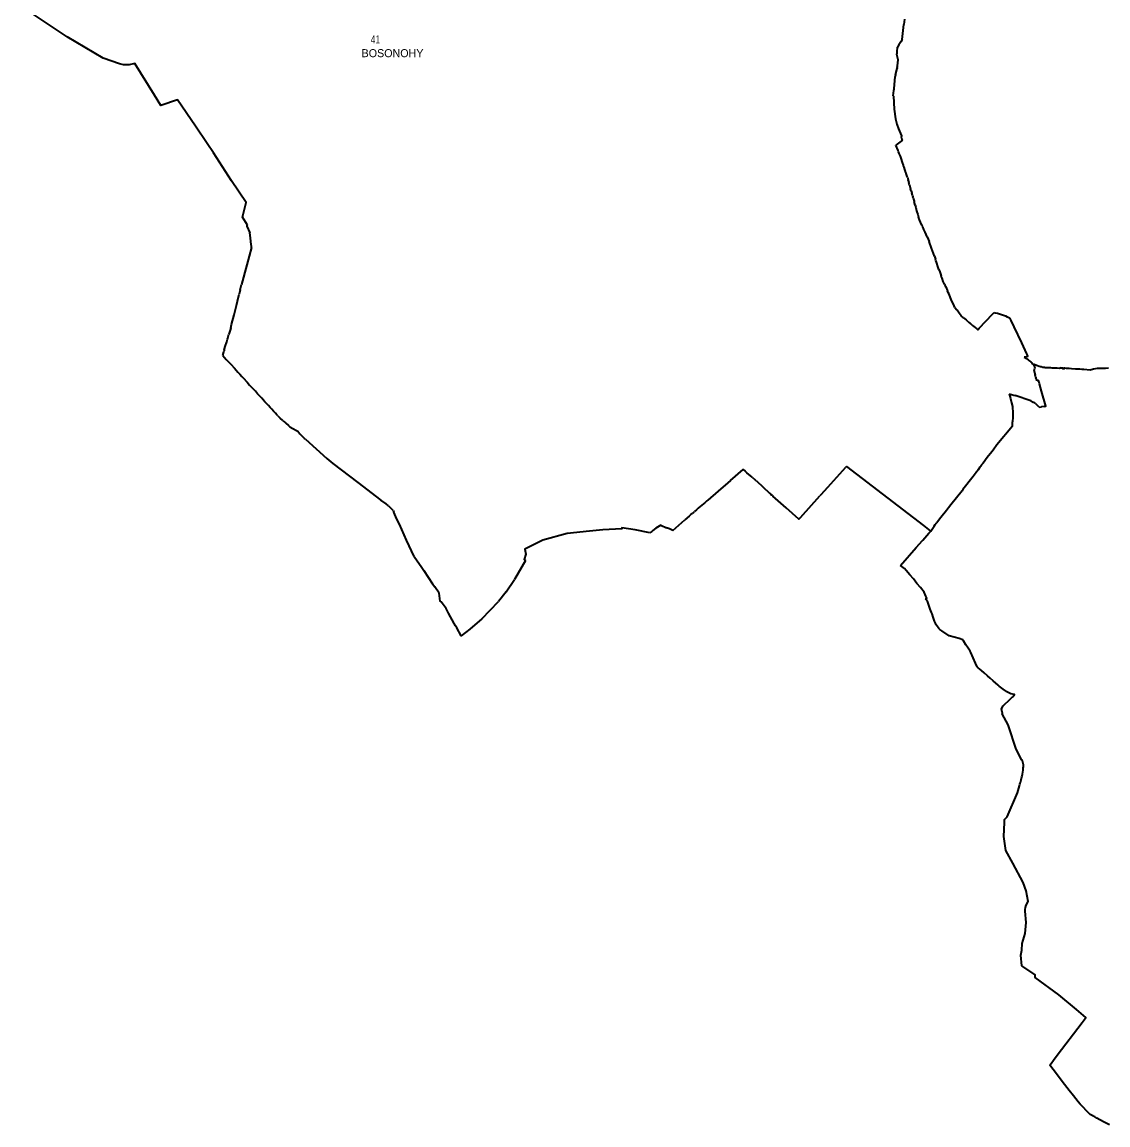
# Model space of a CAD drawing. Extents: x -610940 to -588976, y -1170376 to -1149800.
# Drawn here: x -605598 to -602206, y -1165066 to -1161621 of the extents above; entities that cross this region are included whole.
import ezdxf

# ---------------------------------------------------------------- set-up
doc = ezdxf.new("R2010")
doc.units = 0
doc.header["$LTSCALE"] = 10
doc.layers.add('54', color=7, linetype='Continuous', lineweight=35)
doc.layers.add('55', color=7, linetype='Continuous')
doc.layers.add('56', color=7, linetype='Continuous')

msp = doc.modelspace()

# ---------------------------------------------------------------- linework, layer by layer
at = {"layer": '54'}
for p, q in [((-602841.54, -1161611.08), (-602843.56, -1161628.3)), ((-602848.02, -1161665.8), (-602843.56, -1161628.3)), ((-602853.39, -1161682.08), (-602858.83, -1161691.46)), ((-602849.05, -1161674.6), (-602853.39, -1161682.08)), ((-602849.05, -1161674.6), (-602848.02, -1161665.8)), ((-602864.79, -1161716.8), (-602864.55, -1161713.75)), ((-602864.55, -1161713.75), (-602863.39, -1161699.27)), ((-602858.83, -1161691.46), (-602863.39, -1161699.27)), ((-602863.34, -1161757.46), (-602861.01, -1161738.27)), ((-602873.9, -1161829.26), (-602870.17, -1161790.65)), ((-602869.68, -1161785.03), (-602870.17, -1161790.65)), ((-602869.68, -1161785.03), (-602864.72, -1161765.63)), ((-602863.93, -1161762.34), (-602864.72, -1161765.63)), ((-602863.93, -1161762.34), (-602863.34, -1161757.46)), ((-602876.35, -1161851.36), (-602874.52, -1161834.89)), ((-602874.52, -1161834.89), (-602873.9, -1161829.26)), ((-602873.39, -1161892.28), (-602869.7, -1161922.7)), ((-602848.19, -1161989.75), (-602868.49, -1162005.4)), ((-602849.39, -1161986.61), (-602848.19, -1161989.75)), ((-602861.35, -1162021.88), (-602868.49, -1162005.4)), ((-602859.84, -1162025.51), (-602861.35, -1162021.88)), ((-602857.66, -1162030.75), (-602859.84, -1162025.51)), ((-602855.86, -1162035.3), (-602857.66, -1162030.75)), ((-602854.16, -1162039.6), (-602855.86, -1162035.3)), ((-602852.17, -1162045.58), (-602854.16, -1162039.6)), ((-602847.65, -1162059.11), (-602852.17, -1162045.58)), ((-602847.54, -1162059.44), (-602847.65, -1162059.11)), ((-602844.67, -1162068.05), (-602847.54, -1162059.44)), ((-602844.2, -1162069.45), (-602844.67, -1162068.05)), ((-602842.59, -1162074.23), (-602844.2, -1162069.45)), ((-602840.22, -1162081.28), (-602842.59, -1162074.23)), ((-602838.32, -1162087.1), (-602840.22, -1162081.28)), ((-602836.24, -1162093.4), (-602836.43, -1162092.89)), ((-602835.08, -1162096.62), (-602836.24, -1162093.4)), ((-602833.21, -1162102.71), (-602835.08, -1162096.62)), ((-602832.31, -1162105.64), (-602833.21, -1162102.71)), ((-602832.31, -1162105.64), (-602829.97, -1162114.01)), ((-602829.56, -1162115.49), (-602829.97, -1162114.01)), ((-602829.56, -1162115.49), (-602827.77, -1162122.2)), ((-602826, -1162128.86), (-602827.77, -1162122.2)), ((-602826, -1162128.86), (-602823.4, -1162138.1)), ((-602823.4, -1162138.1), (-602822.26, -1162141.99)), ((-602820.64, -1162147.49), (-602822.26, -1162141.99)), ((-602820.64, -1162147.49), (-602818.77, -1162154.49)), ((-602816.7, -1162161.56), (-602818.77, -1162154.49)), ((-602816.7, -1162161.56), (-602815.44, -1162166.1)), ((-602814.06, -1162171.05), (-602815.44, -1162166.1)), ((-602814.06, -1162171.05), (-602811.29, -1162180.59)), ((-602811.29, -1162180.59), (-602811.07, -1162181.5)), ((-602808.29, -1162192.78), (-602811.07, -1162181.5)), ((-602797.43, -1162229.8), (-602797.33, -1162230.11)), ((-602794.7, -1162238.06), (-602797.33, -1162230.11)), ((-602794.7, -1162238.06), (-602794.62, -1162238.24)), ((-602791.28, -1162245.7), (-602794.62, -1162238.24)), ((-602791.28, -1162245.7), (-602791.15, -1162245.99)), ((-602786.87, -1162255.16), (-602791.15, -1162245.99)), ((-602786.87, -1162255.16), (-602786.66, -1162255.62)), ((-602785.11, -1162259.04), (-602786.66, -1162255.62)), ((-602784.33, -1162260.76), (-602785.11, -1162259.04)), ((-602780.76, -1162268.79), (-602784.33, -1162260.76)), ((-604884.4, -1162294.52), (-604886.23, -1162279.31)), ((-604884.21, -1162296.14), (-604884.4, -1162294.52)), ((-604883.13, -1162305.13), (-604884.21, -1162296.14)), ((-604882.94, -1162306.75), (-604883.13, -1162305.13)), ((-604881.52, -1162324.66), (-604895.91, -1162379.46)), ((-602747.56, -1162352.41), (-602744.76, -1162361.02)), ((-602743.14, -1162365.99), (-602744.76, -1162361.02)), ((-602741.62, -1162370.68), (-602743.14, -1162365.99)), ((-604895.91, -1162379.46), (-604912.07, -1162441)), ((-604916.31, -1162457.12), (-604912.07, -1162441)), ((-602716.8, -1162439.32), (-602713, -1162447.36)), ((-604925.09, -1162492.41), (-604919.57, -1162470.24)), ((-604916.31, -1162457.12), (-604919.57, -1162470.24)), ((-602712.76, -1162447.88), (-602713, -1162447.36)), ((-602712.76, -1162447.88), (-602707.03, -1162460.6)), ((-602704.77, -1162465.61), (-602707.03, -1162460.6)), ((-602684.09, -1162512.03), (-602678.42, -1162519.33)), ((-602678.42, -1162519.33), (-602677.08, -1162521.06)), ((-602656.65, -1162544.64), (-602649.06, -1162550.99)), ((-602566.16, -1162533.28), (-602565.47, -1162532.55)), ((-602565.47, -1162532.55), (-602565.18, -1162532.21)), ((-602565.18, -1162532.21), (-602561.16, -1162527.58)), ((-602552.48, -1162530.16), (-602550.61, -1162530.73)), ((-602548.36, -1162531.42), (-602550.61, -1162530.73)), ((-602538.47, -1162534.36), (-602529.45, -1162536.92)), ((-602529.45, -1162536.92), (-602526.02, -1162538.54)), ((-602526.02, -1162538.54), (-602525.59, -1162538.74)), ((-602525.59, -1162538.74), (-602520.87, -1162541.16)), ((-602516.03, -1162543.64), (-602513.65, -1162544.86)), ((-602513.65, -1162544.86), (-602513.48, -1162544.95)), ((-602513.48, -1162544.95), (-602509.6, -1162553.1)), ((-604946.03, -1162576.58), (-604951.54, -1162595.44)), ((-602642.27, -1162556.87), (-602649.06, -1162550.99)), ((-604971.1, -1162662.46), (-604967.66, -1162650.65)), ((-604966.22, -1162645.7), (-604967.66, -1162650.65)), ((-604966.22, -1162645.7), (-604966.13, -1162645.4)), ((-604966.13, -1162645.4), (-604962.89, -1162634.3)), ((-602476.43, -1162622.68), (-602460.16, -1162656.8)), ((-604960.26, -1162674.3), (-604955.2, -1162679.84)), ((-604955.2, -1162679.84), (-604946.06, -1162689.82)), ((-602466.79, -1162667.39), (-602467.71, -1162667.53)), ((-602467.71, -1162667.53), (-602466.05, -1162668.61)), ((-602455.91, -1162665.72), (-602466.79, -1162667.39)), ((-602466.05, -1162668.61), (-602460.81, -1162672.03)), ((-602460.16, -1162656.8), (-602455.91, -1162665.72)), ((-602452.61, -1162677.74), (-602450.39, -1162679.54)), ((-602449.66, -1162680.13), (-602450.39, -1162679.54)), ((-602449.66, -1162680.13), (-602447.03, -1162682.53)), ((-602447.03, -1162682.53), (-602446.73, -1162682.8)), ((-602438.77, -1162691.76), (-602439.57, -1162690.75)), ((-602436.06, -1162710.3), (-602436.57, -1162712.37)), ((-602436.57, -1162712.37), (-602433.37, -1162723.03)), ((-602434.88, -1162697.32), (-602433.38, -1162699.53)), ((-604886.9, -1162754.48), (-604877.97, -1162764.24)), ((-602431.39, -1162729.68), (-602430.78, -1162731.74)), ((-602427.92, -1162741.35), (-602428.27, -1162740.17)), ((-602422.77, -1162739.74), (-602427.92, -1162741.35)), ((-602422.47, -1162740.73), (-602422.77, -1162739.74)), ((-602421.72, -1162743.19), (-602422.47, -1162740.73)), ((-602420.85, -1162746.01), (-602421.72, -1162743.19)), ((-604868.95, -1162774.09), (-604877.97, -1162764.24)), ((-604861.86, -1162781.84), (-604868.95, -1162774.09)), ((-604854.42, -1162789.97), (-604861.86, -1162781.84)), ((-604849.18, -1162795.7), (-604854.42, -1162789.97)), ((-602514.34, -1162781.62), (-602499.56, -1162785.74)), ((-602514.34, -1162781.62), (-602510.33, -1162796.88)), ((-602499.56, -1162785.74), (-602496.13, -1162786.93)), ((-602446.42, -1162804.12), (-602496.13, -1162786.93)), ((-604844.15, -1162801.2), (-604849.18, -1162795.7)), ((-604839, -1162806.83), (-604844.15, -1162801.2)), ((-604833.75, -1162812.57), (-604839, -1162806.83)), ((-604828.42, -1162818.39), (-604833.75, -1162812.57)), ((-604823.06, -1162824.25), (-604828.42, -1162818.39)), ((-604817.94, -1162829.85), (-604823.06, -1162824.25)), ((-602503.85, -1162821.55), (-602503.76, -1162826.09)), ((-602446.42, -1162804.12), (-602439.23, -1162807.58)), ((-602439.23, -1162807.58), (-602437.79, -1162808.5)), ((-602432.78, -1162811.72), (-602437.79, -1162808.5)), ((-602432.78, -1162811.72), (-602425.56, -1162818.01)), ((-602425.56, -1162818.01), (-602422.61, -1162821.63)), ((-602420.98, -1162823.63), (-602422.61, -1162821.63)), ((-602420.98, -1162823.63), (-602414.56, -1162822.81)), ((-602414.56, -1162822.81), (-602413.78, -1162822.7)), ((-602404.67, -1162821.36), (-602413.78, -1162822.7)), ((-604811.92, -1162836.41), (-604817.94, -1162829.85)), ((-604806.41, -1162842.43), (-604811.92, -1162836.41)), ((-604801.87, -1162847.4), (-604806.41, -1162842.43)), ((-604799.14, -1162850.38), (-604801.87, -1162847.4)), ((-604799.14, -1162850.38), (-604791.13, -1162858.08)), ((-604783.24, -1162865.68), (-604791.13, -1162858.08)), ((-602503.1, -1162854.81), (-602503.81, -1162869.19)), ((-602503.76, -1162826.09), (-602503.51, -1162838.08)), ((-602503.51, -1162838.08), (-602503.27, -1162847.93)), ((-602503.27, -1162847.93), (-602503.1, -1162854.81)), ((-604783.24, -1162865.68), (-604780.12, -1162868.38)), ((-604773.56, -1162874.06), (-604765.78, -1162880.8)), ((-604765.78, -1162880.8), (-604760.88, -1162885.05)), ((-604760.88, -1162885.05), (-604756.9, -1162887.25)), ((-604756.9, -1162887.25), (-604755.65, -1162887.94)), ((-604755.65, -1162887.94), (-604736.16, -1162898.71)), ((-602504.53, -1162882.75), (-602552.52, -1162941.55)), ((-602504.53, -1162882.75), (-602503.81, -1162869.19)), ((-604736.16, -1162898.71), (-604729.94, -1162907.53)), ((-604729.94, -1162907.53), (-604725.12, -1162912.11)), ((-604725.12, -1162912.11), (-604725.07, -1162912.16)), ((-604712.67, -1162923.95), (-604715.38, -1162921.37)), ((-604627.07, -1162999.7), (-604549.42, -1163058.75)), ((-603081.05, -1163073.37), (-603024.85, -1163010.72)), ((-603023.29, -1163008.98), (-603024.85, -1163010.72)), ((-604549.42, -1163058.75), (-604476.95, -1163113.85)), ((-603384.63, -1163052.38), (-603393.75, -1163060.26)), ((-603317.07, -1163042.9), (-603307.04, -1163051.51)), ((-603304.12, -1163054.01), (-603307.04, -1163051.51)), ((-603253.95, -1163100.18), (-603256.38, -1163098.15)), ((-603253.95, -1163100.18), (-603252.5, -1163101.44)), ((-603104.78, -1163099.82), (-603105.78, -1163100.95)), ((-603102.02, -1163096.74), (-603081.05, -1163073.37)), ((-604460.8, -1163126.14), (-604476.95, -1163113.85)), ((-604453.3, -1163131.84), (-604460.8, -1163126.14)), ((-604453.3, -1163131.84), (-604444.65, -1163140.59)), ((-603458.49, -1163116.2), (-603465.49, -1163122.22)), ((-603455.92, -1163114), (-603458.49, -1163116.2)), ((-603210.77, -1163137.83), (-603252.5, -1163101.44)), ((-603165.94, -1163167.99), (-603105.78, -1163100.95)), ((-604438.88, -1163146.42), (-604444.65, -1163140.59)), ((-604438.88, -1163146.42), (-604437.7, -1163149.39)), ((-604437.7, -1163149.39), (-604436.41, -1163152.19)), ((-604430.12, -1163165.9), (-604436.41, -1163152.19)), ((-603514.1, -1163164.13), (-603527.69, -1163175.93)), ((-603514.1, -1163164.13), (-603508.38, -1163159.16)), ((-603508.38, -1163159.16), (-603504.85, -1163156.1)), ((-603500.59, -1163152.39), (-603504.85, -1163156.1)), ((-603499.78, -1163151.68), (-603500.59, -1163152.39)), ((-603499.78, -1163151.68), (-603497.3, -1163149.54)), ((-603491.48, -1163144.54), (-603497.3, -1163149.54)), ((-603602.66, -1163192.04), (-603584.41, -1163200.21)), ((-603575.28, -1163204.3), (-603584.41, -1163200.21)), ((-603565.43, -1163208.71), (-603527.69, -1163175.93)), ((-602782.33, -1163193.36), (-602760.88, -1163209.77)), ((-602740.95, -1163184.74), (-602741.08, -1163184.92)), ((-603565.43, -1163208.71), (-603575.28, -1163204.3)), ((-602759.69, -1163210.68), (-602760.88, -1163209.77)), ((-604025.16, -1163302.29), (-604059.89, -1163361.8)), ((-604028.45, -1163300.54), (-604025.16, -1163302.29)), ((-604315.27, -1163375.29), (-604308.54, -1163385.19)), ((-604085.63, -1163400.77), (-604059.89, -1163361.8)), ((-604295.38, -1163404.54), (-604308.54, -1163385.19)), ((-604085.63, -1163400.77), (-604109.33, -1163430.7)), ((-604161.24, -1163484.47), (-604109.33, -1163430.7))]:
    msp.add_line(p, q, dxfattribs=at)
for points in [[(-604893.85, -1162255.26), (-604909.6, -1162229.74), (-604897.42, -1162184.3), (-604943.47, -1162116.1), (-605000.09, -1162029.59), (-605019.7, -1161999.98), (-605055.71, -1161945.84), (-605111.96, -1161863.47), (-605163.86, -1161881.41), (-605183.99, -1161848.88), (-605245.59, -1161749.86), (-605263.57, -1161754.01), (-605281.37, -1161754.59), (-605293.4, -1161750.61), (-605344.01, -1161732.99), (-605456.43, -1161666.79), (-605597.77, -1161573.45)], [(-602861.01, -1161738.27), (-602865.2, -1161721.92), (-602864.79, -1161716.8)], [(-602876.35, -1161851.36), (-602876.22, -1161852.2), (-602873.39, -1161892.28)], [(-602869.7, -1161922.7), (-602865.28, -1161939.27), (-602860.5, -1161953.86), (-602851.2, -1161976.34), (-602851.82, -1161980.87), (-602851.14, -1161982.04), (-602849.39, -1161986.61)], [(-602836.43, -1162092.89), (-602837.94, -1162088.27), (-602838.32, -1162087.1)], [(-602808.29, -1162192.78), (-602806.5, -1162199.92), (-602803.76, -1162210.79), (-602802.99, -1162213.87), (-602800.21, -1162221.94), (-602797.43, -1162229.8)], [(-604893.85, -1162255.26), (-604895.27, -1162257.94), (-604886.23, -1162279.31)], [(-602770.41, -1162291.92), (-602777.17, -1162276.86), (-602780.76, -1162268.79)], [(-604881.52, -1162324.66), (-604881.09, -1162322.11), (-604882.94, -1162306.75)], [(-602770.41, -1162291.92), (-602767.64, -1162298.97), (-602764.84, -1162306.45)], [(-602747.56, -1162352.41), (-602750.35, -1162343.82), (-602753.7, -1162334.99), (-602756.96, -1162326.74), (-602764.84, -1162306.45)], [(-602734.01, -1162393.51), (-602736.3, -1162387.06), (-602741.62, -1162370.68)], [(-602734.01, -1162393.51), (-602731.17, -1162401.33), (-602729.09, -1162407.43), (-602726.6, -1162414.23)], [(-602716.8, -1162439.32), (-602720.73, -1162430.91), (-602724.28, -1162420.65), (-602726.6, -1162414.23)], [(-602684.09, -1162512.03), (-602688.64, -1162502.12), (-602693.1, -1162492.09), (-602697.34, -1162482.1), (-602702.25, -1162471.05), (-602704.77, -1162465.61)], [(-604946.03, -1162576.58), (-604943.14, -1162564.95), (-604935.68, -1162535), (-604928.37, -1162505.58), (-604925.09, -1162492.41)], [(-602656.65, -1162544.64), (-602664.22, -1162538.08), (-602670.43, -1162529.64), (-602677.08, -1162521.06)], [(-602642.27, -1162556.87), (-602636.47, -1162562.05), (-602635.33, -1162562.78), (-602632.18, -1162565.5), (-602628.58, -1162568.82), (-602624.8, -1162571.67), (-602621.18, -1162574.77), (-602615.89, -1162579.18), (-602614.83, -1162580.07), (-602613.78, -1162580.79), (-602612.44, -1162582.06), (-602611.4, -1162580.96), (-602607.94, -1162577.32), (-602566.16, -1162533.28)], [(-602561.16, -1162527.58), (-602558.24, -1162528.57), (-602552.48, -1162530.16)], [(-602548.36, -1162531.42), (-602544.86, -1162532.55), (-602541.46, -1162533.51), (-602538.47, -1162534.36)], [(-602520.87, -1162541.16), (-602519.73, -1162541.75), (-602516.03, -1162543.64)], [(-602509.6, -1162553.1), (-602500.33, -1162572.55), (-602476.43, -1162622.68)], [(-604962.89, -1162634.3), (-604961.99, -1162631.23), (-604959.62, -1162623.11), (-604958.49, -1162619.23), (-604956.11, -1162611.09), (-604955.2, -1162607.99), (-604951.54, -1162595.44)], [(-604971.1, -1162662.46), (-604965.7, -1162668.36), (-604960.26, -1162674.3)], [(-602460.81, -1162672.03), (-602454.98, -1162675.98), (-602452.61, -1162677.74)], [(-602446.73, -1162682.8), (-602443.86, -1162685.62), (-602441.17, -1162688.72)], [(-604946.06, -1162689.82), (-604934.73, -1162702.21), (-604923.47, -1162714.51), (-604917.87, -1162720.63), (-604911.3, -1162727.82), (-604907.59, -1162731.87), (-604894.85, -1162745.79), (-604886.9, -1162754.48)], [(-602416.23, -1162697.89), (-602420.61, -1162696.91), (-602425.6, -1162694.91), (-602429.41, -1162693.39), (-602436.51, -1162690.54), (-602437.33, -1162690.21), (-602439.57, -1162690.75), (-602441.17, -1162688.72)], [(-602438.77, -1162691.76), (-602436.03, -1162695.63), (-602434.88, -1162697.32)], [(-602436.06, -1162710.3), (-602433.92, -1162701.69), (-602433.38, -1162699.53)], [(-602281.15, -1162706.53), (-602288.01, -1162705.78), (-602294.08, -1162705.38), (-602307.05, -1162704.53), (-602319.87, -1162703.68), (-602327.45, -1162703.41), (-602335.32, -1162703.13), (-602340.74, -1162701.41), (-602340.76, -1162702.34), (-602342.57, -1162702.3), (-602342.6, -1162703.53), (-602346.21, -1162703.44), (-602346.38, -1162703.44), (-602346.36, -1162702.56), (-602346.35, -1162702.2), (-602346.85, -1162702.19), (-602348.18, -1162702.16), (-602349.05, -1162702.13), (-602351.74, -1162702.15), (-602351.76, -1162701), (-602352.23, -1162701.11), (-602352.4, -1162701.15), (-602355.55, -1162701.9), (-602358.83, -1162702.62), (-602364.34, -1162702.22), (-602368.17, -1162702), (-602372.44, -1162701.49), (-602376.2, -1162701.43), (-602380.04, -1162701.38), (-602384.01, -1162701.34), (-602388.67, -1162701.15), (-602397.32, -1162700.79), (-602401.57, -1162700.4), (-602403.88, -1162700.18), (-602405.09, -1162700.07), (-602407.03, -1162699.69), (-602408.03, -1162699.46), (-602409, -1162699.28), (-602414.83, -1162698.16), (-602416.23, -1162697.89)], [(-602204.18, -1162701.83), (-602213.34, -1162702.56), (-602216.78, -1162702.83), (-602225.41, -1162702.81), (-602232.66, -1162702.79), (-602239.69, -1162702.76), (-602250.67, -1162705.45), (-602261.37, -1162708.07), (-602281.15, -1162706.53)], [(-602431.39, -1162729.68), (-602431.93, -1162727.88), (-602433.37, -1162723.03)], [(-602428.27, -1162740.17), (-602429.41, -1162736.36), (-602430.78, -1162731.74)], [(-602404.67, -1162821.36), (-602399.58, -1162820.49), (-602413.77, -1162774.12), (-602419.29, -1162751.13), (-602420.85, -1162746.01)], [(-602510.33, -1162796.88), (-602506.93, -1162809.83), (-602503.85, -1162821.55)], [(-604780.12, -1162868.38), (-604777.26, -1162870.86), (-604773.56, -1162874.06)], [(-604725.07, -1162912.16), (-604723.44, -1162913.71), (-604718.44, -1162918.46), (-604715.38, -1162921.37)], [(-604712.67, -1162923.95), (-604646.12, -1162983.87), (-604627.07, -1162999.7)], [(-602552.52, -1162941.55), (-602556.78, -1162947.26), (-602560.49, -1162952.16), (-602565, -1162958.01), (-602568.92, -1162962.97), (-602582.72, -1162980.95), (-602588.8, -1162988.61), (-602590.71, -1162991.17), (-602592.89, -1162993.99), (-602596.96, -1162999.27), (-602599.07, -1163002.19), (-602601.48, -1163005.38), (-602603.03, -1163007.52), (-602606.03, -1163011.61), (-602611.84, -1163019.73), (-602613.55, -1163022.13), (-602615.7, -1163024.9), (-602617.33, -1163027.36), (-602626.97, -1163040.5), (-602658.87, -1163081.2)], [(-603384.63, -1163052.38), (-603345.46, -1163018.52), (-603339.42, -1163023.71)], [(-603317.07, -1163042.9), (-603333.64, -1163028.67), (-603339.42, -1163023.71)], [(-603023.29, -1163008.98), (-603022.58, -1163009.52), (-602782.33, -1163193.36)], [(-603393.75, -1163060.26), (-603423.85, -1163086.28), (-603455.92, -1163114)], [(-603304.12, -1163054.01), (-603263, -1163092.03), (-603260.01, -1163094.8), (-603256.38, -1163098.15)], [(-603102.02, -1163096.74), (-603103.4, -1163098.27), (-603104.78, -1163099.82)], [(-602658.87, -1163081.2), (-602661.82, -1163084.96), (-602696.26, -1163128.9)], [(-603465.49, -1163122.22), (-603468.1, -1163124.46), (-603475.19, -1163130.55), (-603478.46, -1163133.36), (-603485.58, -1163139.47), (-603488.21, -1163141.73), (-603491.48, -1163144.54)], [(-602696.26, -1163128.9), (-602703.74, -1163138.46), (-602710.26, -1163146.64), (-602727.47, -1163168.13), (-602731.9, -1163173.67), (-602740.95, -1163184.74)], [(-604372.92, -1163290.5), (-604396.48, -1163239.18), (-604419.33, -1163189.42), (-604424.81, -1163177.47), (-604430.12, -1163165.9)], [(-603165.94, -1163167.99), (-603171.37, -1163173.73), (-603210.77, -1163137.83)], [(-603636.86, -1163216.51), (-603683.12, -1163206.77), (-603724.08, -1163201.02), (-603723.91, -1163203.68), (-603783.99, -1163206.56), (-603825.26, -1163211.54), (-603895.26, -1163218.28), (-603971.45, -1163239.18), (-604027.48, -1163267.83), (-604024.6, -1163282.98), (-604029.54, -1163299.96), (-604028.45, -1163300.54)], [(-603602.66, -1163192.04), (-603617.82, -1163201.77), (-603627.25, -1163209.07)], [(-602853.51, -1163318.05), (-602805.05, -1163262.6), (-602785.62, -1163240.35), (-602784.54, -1163239.12), (-602765.91, -1163217.8), (-602760.68, -1163211.82), (-602759.69, -1163210.68), (-602748.62, -1163195.36), (-602745.31, -1163190.78), (-602743.27, -1163187.95), (-602742.77, -1163187.26), (-602741.08, -1163184.92)], [(-603627.25, -1163209.07), (-603631.17, -1163212.1), (-603636.86, -1163216.51)], [(-604372.92, -1163290.5), (-604349.51, -1163324.93), (-604343.15, -1163334.28), (-604315.27, -1163375.29)], [(-602610.83, -1163637.64), (-602614.91, -1163634.64), (-602619.62, -1163623.74), (-602633.98, -1163590.47), (-602636.01, -1163585.76), (-602642.5, -1163576.62), (-602649.56, -1163566.68), (-602656.73, -1163553.29), (-602657.96, -1163551.78), (-602659.16, -1163550.91), (-602670.86, -1163546.52), (-602701.86, -1163537.81), (-602724.89, -1163522.8), (-602731.34, -1163518.58), (-602733.85, -1163514.9), (-602736.2, -1163511.74), (-602742.19, -1163503.58), (-602745.05, -1163498.79), (-602747.29, -1163492.65), (-602751.82, -1163480.25), (-602754.53, -1163469.82), (-602757.28, -1163465.69), (-602760.78, -1163455.27), (-602769.23, -1163430.15), (-602771.14, -1163428.82), (-602771.6, -1163428.1), (-602773.63, -1163424.49), (-602774.7, -1163422.63), (-602771.56, -1163420.56), (-602774.34, -1163414.14), (-602780.34, -1163401.97), (-602791.24, -1163387.47), (-602802.53, -1163374.24), (-602813.18, -1163360.08), (-602825.19, -1163347.06), (-602836.68, -1163333.47), (-602841.5, -1163327.56), (-602849.39, -1163321.31), (-602849.79, -1163321), (-602853.51, -1163318.05)], [(-604270.09, -1163458.7), (-604273.42, -1163452.77), (-604288.72, -1163432.31), (-604291.57, -1163429.72), (-604295.38, -1163404.54)], [(-604240.22, -1163513.29), (-604243.97, -1163506.43), (-604247.65, -1163499.71), (-604265.59, -1163466.92), (-604270.09, -1163458.7)], [(-604161.24, -1163484.47), (-604199.29, -1163516.76), (-604226.63, -1163538.13), (-604240.22, -1163513.29)], [(-602482.64, -1164006.37), (-602481.19, -1164001.64), (-602480.2, -1163997.86), (-602479.47, -1163995.81), (-602477.46, -1163988.02), (-602474.84, -1163978.87), (-602474.25, -1163975.26), (-602473.23, -1163969.75), (-602471.1, -1163957.69), (-602470.47, -1163950.62), (-602470.11, -1163947.11), (-602469.79, -1163941.14), (-602473.06, -1163929.01), (-602473.77, -1163926.92), (-602476.4, -1163925.37), (-602493.98, -1163889.07), (-602515.93, -1163821.98), (-602517.41, -1163816.59), (-602536.72, -1163782.21), (-602535.66, -1163780.03), (-602536.85, -1163776.66), (-602538.06, -1163765.8), (-602533.24, -1163756.42), (-602510.97, -1163735.68), (-602503.68, -1163729.02), (-602502.76, -1163728.18), (-602497.62, -1163721.23), (-602508.79, -1163718.76), (-602517.41, -1163714.8), (-602523.77, -1163711.55), (-602525.94, -1163710.21), (-602533.45, -1163704.53), (-602545.32, -1163695.16), (-602548.66, -1163692.45), (-602564.8, -1163678.42), (-602574.38, -1163670.07), (-602582.53, -1163662.74), (-602592.6, -1163653.71), (-602600.61, -1163646.64), (-602610.83, -1163637.64)], [(-602326.9, -1164958.48), (-602334.45, -1164949.03), (-602342.06, -1164939.44), (-602349.08, -1164930.08), (-602366.72, -1164906.59), (-602387.33, -1164879.13), (-602383.34, -1164873.85), (-602375.88, -1164863.98), (-602364.07, -1164848.36), (-602286.77, -1164746.13), (-602276.85, -1164733.08), (-602274.61, -1164730.15), (-602304.42, -1164705.37), (-602358.92, -1164659.92), (-602433.71, -1164605.27), (-602432.88, -1164597.47), (-602472.19, -1164571.03), (-602474.69, -1164568.93), (-602477.79, -1164535.98), (-602475.05, -1164520.41), (-602473.75, -1164498.8), (-602464.38, -1164468.27), (-602461.33, -1164434.05), (-602464.84, -1164398.61), (-602464.86, -1164392.89), (-602463.6, -1164386.59), (-602460.94, -1164379.37), (-602454.78, -1164367.8), (-602461.85, -1164335.23), (-602470.79, -1164309.06), (-602503.38, -1164248.45), (-602525.24, -1164208.39), (-602531.28, -1164165.19), (-602529.14, -1164121.66), (-602528.77, -1164113.6), (-602528.61, -1164112.02), (-602520.76, -1164103.96), (-602488.38, -1164028.65), (-602486.78, -1164021.16), (-602482.64, -1164006.37)], [(-602201.38, -1165066.1), (-602208.95, -1165061.98), (-602219.59, -1165056.18), (-602240.73, -1165044.67), (-602247.15, -1165041.18), (-602252.12, -1165038.48), (-602253.55, -1165037.75), (-602261.34, -1165033.75), (-602265.03, -1165029.92), (-602269.88, -1165024.92), (-602286.28, -1165007.9), (-602293.12, -1165000.81), (-602298.78, -1164993.72), (-602313.93, -1164974.73), (-602326.9, -1164958.48)]]:
    msp.add_lwpolyline(points, dxfattribs=at)

# ---------------------------------------------------------------- texts
at = {"layer": '55'}
msp.add_text('BOSONOHY ', height=25, dxfattribs=at).set_placement((-604537.19, -1161730.28))
at = {"layer": '56', "width": 0.8}
msp.add_text('41 ', height=25, dxfattribs=at).set_placement((-604508.94, -1161687.44))

doc.saveas('drawing.dxf')
